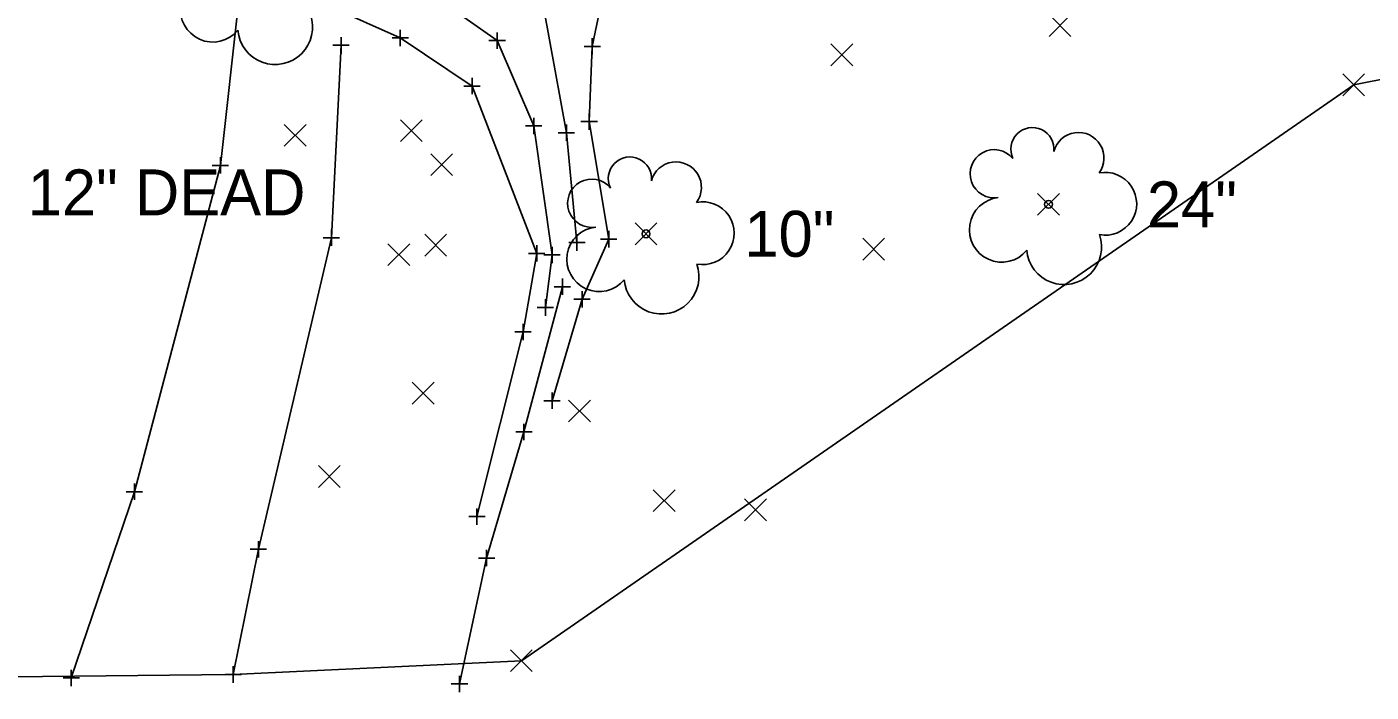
# Model space of a CAD drawing. Extents: x 160138 to 160780, y 488720 to 491073.
# Drawn here: x 160535.3 to 160617.3, y 489637.2 to 489677.7 of the extents above; entities that cross this region are included whole.
import ezdxf

# ---------------------------------------------------------------- set-up
doc = ezdxf.new("R2010")
doc.units = 0
for name, color, linetype in [('_CIVIL_CONSTRUCTION', 7, 'Continuous'), ('GE_X_Alignment_500_Distances', 7, 'Continuous'), ('SC_Scratch1', 7, 'Continuous'), ('SV_P_Control_Cells_Set', 7, 'Continuous'), ('SV_P_Mon_Cells_Set', 7, 'Continuous'), ('SV_X_Random_Point', 7, 'Continuous'), ('SV_X_Terrain_Boundary', 7, 'Continuous'), ('VG_X_Text', 7, 'Continuous')]:
    doc.layers.add(name, color=color, linetype=linetype)

msp = doc.modelspace()

# ---------------------------------------------------------------- linework, layer by layer
at = {"layer": '_CIVIL_CONSTRUCTION'}
for p, q in [((160597.61, 489677.14), (160598.944, 489678.475)), ((160597.61, 489678.475), (160598.944, 489677.14)), ((160584.311, 489675.357), (160585.644, 489676.692)), ((160584.311, 489676.692), (160585.644, 489675.357)), ((160615.522, 489673.516), (160616.856, 489674.851)), ((160615.522, 489674.851), (160616.856, 489673.516)), ((160550.966, 489670.443), (160552.3, 489671.778)), ((160550.966, 489671.778), (160552.3, 489670.443)), ((160558.058, 489670.724), (160559.391, 489672.059)), ((160558.058, 489672.059), (160559.391, 489670.724)), ((160559.907, 489668.655), (160561.241, 489669.989)), ((160559.907, 489669.989), (160561.241, 489668.655)), ((160596.914, 489666.233), (160598.247, 489667.568)), ((160596.914, 489667.568), (160598.247, 489666.233)), ((160572.367, 489664.439), (160573.7, 489665.774)), ((160572.367, 489665.774), (160573.7, 489664.439)), ((160557.293, 489663.168), (160558.626, 489664.503)), ((160557.293, 489664.503), (160558.626, 489663.168)), ((160559.537, 489663.742), (160560.87, 489665.077)), ((160559.537, 489665.077), (160560.87, 489663.742)), ((160586.247, 489663.501), (160587.58, 489664.836)), ((160586.247, 489664.836), (160587.58, 489663.501)), ((160558.773, 489654.728), (160560.106, 489656.063)), ((160558.773, 489656.063), (160560.106, 489654.728)), ((160568.308, 489653.638), (160569.642, 489654.973)), ((160568.308, 489654.973), (160569.642, 489653.638)), ((160553.056, 489649.635), (160554.39, 489650.97)), ((160553.056, 489650.97), (160554.39, 489649.635)), ((160573.472, 489648.165), (160574.806, 489649.5)), ((160573.472, 489649.5), (160574.806, 489648.165)), ((160579.049, 489647.615), (160580.383, 489648.95)), ((160579.049, 489648.95), (160580.383, 489647.615)), ((160564.767, 489638.413), (160566.1, 489639.748)), ((160564.767, 489639.748), (160566.1, 489638.413))]:
    msp.add_line(p, q, dxfattribs=at)
at = {"layer": 'GE_X_Alignment_500_Distances'}
for points in [[(160621.534, 489717.15), (160606.181, 489710.759), (160597.835, 489707.435), (160587.92, 489704.491), (160584.396, 489701.774), (160576.406, 489698.274), (160571.095, 489699.657), (160571.143, 489703.736), (160568.43, 489703.792), (160567.108, 489700.473), (160566.216, 489695.724), (160561.396, 489691.947), (160554.509, 489692.134), (160553.007, 489689.884), (160552.633, 489686.649), (160552.379, 489683.318), (160552.332, 489681.352), (160553.749, 489678.967), (160558.048, 489677.046), (160562.424, 489674.113), (160566.368, 489663.913), (160565.537, 489659.127), (160562.724, 489647.863)], [(160567.306, 489654.928), (160569.133, 489661.115), (160570.764, 489664.778), (160569.567, 489671.947), (160569.755, 489676.53), (160570.988, 489682.463), (160577.363, 489688.561), (160592.024, 489693.602), (160606.811, 489697.077), (160621.483, 489700.054)]]:
    msp.add_lwpolyline(points, dxfattribs=at)
at = {"layer": 'SC_Scratch1'}
for centre in [(160597.581, 489666.901), (160573.034, 489665.106)]:
    msp.add_circle(centre, 0.24, dxfattribs=at)
for centre, radius, start, end in [((160546.617, 489678.769), 1.974, 96.17219, 320.57371), ((160550.417, 489677.713), 2.284, 184.94757, 19.45715), ((160596.597, 489670.268), 1.317, 354.0047, 205.97412), ((160599.407, 489669.73), 1.553, 323.82996, 165.0376), ((160594.271, 489668.765), 1.471, 39.06254, 279.54124), ((160572.05, 489668.474), 1.317, 354.0047, 205.97412), ((160574.86, 489667.935), 1.553, 323.82996, 165.0376), ((160569.724, 489666.97), 1.471, 39.06254, 279.54124), ((160601.041, 489666.937), 1.915, 259.14531, 101.45961), ((160576.494, 489665.142), 1.915, 259.14531, 101.45961), ((160594.727, 489665.352), 1.974, 96.17219, 320.57371), ((160570.18, 489663.558), 1.974, 96.17219, 320.57371), ((160598.527, 489664.296), 2.284, 184.94757, 19.45715), ((160573.98, 489662.501), 2.284, 184.94757, 19.45715)]:
    msp.add_arc(centre, radius, start, end, dxfattribs=at)
at = {"layer": 'SV_P_Control_Cells_Set'}
for points in [[(160575.398, 489688.469), (160572.912, 489687.162), (160569.643, 489683.078), (160566.808, 489678.832), (160568.176, 489671.267), (160568.821, 489664.576)], [(160555.352, 489683.246), (160559.345, 489680.149), (160563.956, 489676.888), (160566.188, 489671.679), (160567.307, 489663.814), (160566.9, 489660.613)], [(160548.197, 489679.349), (160547.077, 489669.28), (160541.837, 489649.382), (160537.983, 489638.031)], [(160554.44, 489676.597), (160553.848, 489664.869), (160549.397, 489645.872), (160547.865, 489638.238)]]:
    msp.add_lwpolyline(points, dxfattribs=at)
at = {"layer": 'SV_P_Mon_Cells_Set'}
msp.add_lwpolyline([(160561.659, 489637.663), (160563.313, 489645.339), (160565.592, 489653.023), (160567.932, 489661.879)], dxfattribs=at)
at = {"layer": 'SV_X_Random_Point'}
for p, q in [((160558.048, 489677.546), (160558.048, 489676.546)), ((160563.956, 489677.388), (160563.956, 489676.388)), ((160553.94, 489676.597), (160554.94, 489676.597)), ((160554.44, 489677.097), (160554.44, 489676.097)), ((160554.44, 489676.597), (160554.44, 489676.597)), ((160557.548, 489677.046), (160558.548, 489677.046)), ((160558.048, 489677.046), (160558.048, 489677.046)), ((160563.456, 489676.888), (160564.456, 489676.888)), ((160563.956, 489676.888), (160563.956, 489676.888)), ((160569.755, 489677.03), (160569.755, 489676.03)), ((160569.255, 489676.53), (160570.255, 489676.53)), ((160569.755, 489676.53), (160569.755, 489676.53)), ((160561.924, 489674.113), (160562.924, 489674.113)), ((160562.424, 489674.613), (160562.424, 489673.613)), ((160562.424, 489674.113), (160562.424, 489674.113)), ((160565.688, 489671.679), (160566.688, 489671.679)), ((160566.188, 489672.179), (160566.188, 489671.179)), ((160566.188, 489671.679), (160566.188, 489671.679)), ((160568.176, 489671.767), (160568.176, 489670.767)), ((160569.067, 489671.947), (160570.067, 489671.947)), ((160569.567, 489672.447), (160569.567, 489671.447)), ((160569.567, 489671.947), (160569.567, 489671.947)), ((160567.676, 489671.267), (160568.676, 489671.267)), ((160568.176, 489671.267), (160568.176, 489671.267)), ((160546.577, 489669.28), (160547.577, 489669.28)), ((160547.077, 489669.78), (160547.077, 489668.78)), ((160547.077, 489669.28), (160547.077, 489669.28)), ((160553.848, 489665.369), (160553.848, 489664.369)), ((160570.764, 489665.278), (160570.764, 489664.278)), ((160553.348, 489664.869), (160554.348, 489664.869)), ((160553.848, 489664.869), (160553.848, 489664.869)), ((160566.368, 489664.413), (160566.368, 489663.413)), ((160567.307, 489664.314), (160567.307, 489663.314)), ((160568.321, 489664.576), (160569.321, 489664.576)), ((160568.821, 489665.076), (160568.821, 489664.076)), ((160568.821, 489664.576), (160568.821, 489664.576)), ((160570.264, 489664.778), (160571.264, 489664.778)), ((160570.764, 489664.778), (160570.764, 489664.778)), ((160565.868, 489663.913), (160566.868, 489663.913)), ((160566.368, 489663.913), (160566.368, 489663.913)), ((160566.807, 489663.814), (160567.807, 489663.814)), ((160567.307, 489663.814), (160567.307, 489663.814)), ((160567.432, 489661.879), (160568.432, 489661.879)), ((160567.932, 489662.379), (160567.932, 489661.379)), ((160567.932, 489661.879), (160567.932, 489661.879)), ((160566.9, 489661.113), (160566.9, 489660.113)), ((160568.633, 489661.115), (160569.633, 489661.115)), ((160569.133, 489661.615), (160569.133, 489660.615)), ((160569.133, 489661.115), (160569.133, 489661.115)), ((160566.4, 489660.613), (160567.4, 489660.613)), ((160566.9, 489660.613), (160566.9, 489660.613)), ((160565.537, 489659.627), (160565.537, 489658.627)), ((160565.037, 489659.127), (160566.037, 489659.127)), ((160565.537, 489659.127), (160565.537, 489659.127)), ((160567.306, 489655.428), (160567.306, 489654.428)), ((160566.806, 489654.928), (160567.806, 489654.928)), ((160567.306, 489654.928), (160567.306, 489654.928)), ((160565.092, 489653.023), (160566.092, 489653.023)), ((160565.592, 489653.523), (160565.592, 489652.523)), ((160565.592, 489653.023), (160565.592, 489653.023)), ((160541.837, 489649.882), (160541.837, 489648.882)), ((160541.337, 489649.382), (160542.337, 489649.382)), ((160541.837, 489649.382), (160541.837, 489649.382)), ((160562.224, 489647.863), (160563.224, 489647.863)), ((160562.724, 489648.363), (160562.724, 489647.363)), ((160562.724, 489647.863), (160562.724, 489647.863)), ((160549.397, 489646.372), (160549.397, 489645.372)), ((160548.897, 489645.872), (160549.897, 489645.872)), ((160549.397, 489645.872), (160549.397, 489645.872)), ((160563.313, 489645.839), (160563.313, 489644.839)), ((160562.813, 489645.339), (160563.813, 489645.339)), ((160563.313, 489645.339), (160563.313, 489645.339)), ((160537.483, 489638.031), (160538.483, 489638.031)), ((160537.983, 489638.531), (160537.983, 489637.531)), ((160537.983, 489638.031), (160537.983, 489638.031)), ((160547.365, 489638.238), (160548.365, 489638.238)), ((160547.865, 489638.738), (160547.865, 489637.738)), ((160547.865, 489638.238), (160547.865, 489638.238)), ((160561.659, 489638.163), (160561.659, 489637.163)), ((160561.159, 489637.663), (160562.159, 489637.663)), ((160561.659, 489637.663), (160561.659, 489637.663))]:
    msp.add_line(p, q, dxfattribs=at)
at = {"layer": 'SV_X_Terrain_Boundary'}
msp.add_lwpolyline([(160514.912, 489637.894), (160547.865, 489638.238), (160565.434, 489639.08), (160616.189, 489674.183), (160652.272, 489681.356), (160684.014, 489678.351), (160707.031, 489678.823), (160736.83, 489679.671), (160750.025, 489679.19), (160759.846, 489681.649), (160765.268, 489684.51), (160772.898, 489693.362), (160771.249, 489707.538), (160769.281, 489717.032), (160767.493, 489724.397), (160754.691, 489734.763), (160746.199, 489734.784), (160717.641, 489733.306), (160642.598, 489754.256), (160573.958, 489735.815), (160560.406, 489729.318), (160491.054, 489700.611)], dxfattribs=at)

# ---------------------------------------------------------------- texts
at = {"layer": 'VG_X_Text'}
for s, p in [('12" DEAD', (160535.329, 489666.231)), ('24"', (160603.581, 489665.501)), ('10"', (160579.034, 489663.706))]:
    msp.add_text(s, height=2.8, dxfattribs=at).set_placement(p)

doc.saveas('drawing.dxf')
